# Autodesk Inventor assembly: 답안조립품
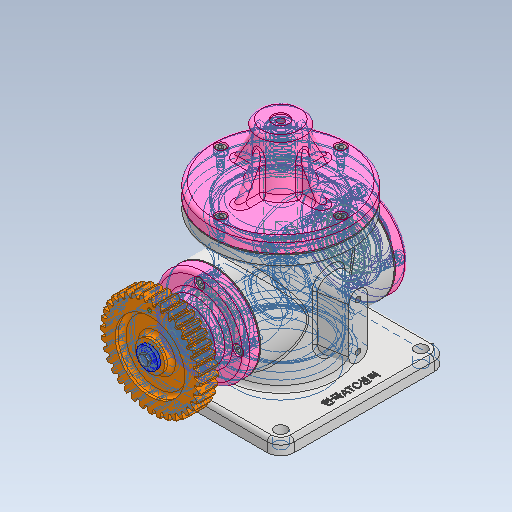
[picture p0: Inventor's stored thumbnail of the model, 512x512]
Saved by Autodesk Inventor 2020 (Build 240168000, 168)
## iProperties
Created: 2020-12
Part Number: 답안조립품
Document SubType Name: Assembly
Designer: USER
Author: USER
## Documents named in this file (21)
- C:\Users\USER\Desktop\601206V1034\답안조립품.iam
- C:\Users\USER\Desktop\601206V1034\본체.ipt
- C:\Users\USER\Desktop\601206V1034\E-링.ipt
- C:\Users\USER\Desktop\601206V1034\개스킷 A.ipt
- C:\Users\USER\Desktop\601206V1034\개스킷 B.ipt
- C:\Users\USER\Desktop\601206V1034\덮개.ipt
- C:\Users\USER\Desktop\601206V1034\뒤커버.ipt
- C:\Users\USER\Desktop\601206V1034\링크.ipt
- C:\Users\USER\Desktop\601206V1034\베어링 17 x 40 x 12.ipt
- C:\Users\USER\Desktop\601206V1034\볼트 M4 x 10.ipt
- C:\Users\USER\Desktop\601206V1034\스퍼기어.ipt
- C:\Users\USER\Desktop\601206V1034\슬라이더.ipt
- C:\Users\USER\Desktop\601206V1034\앞커버.ipt
- C:\Users\USER\Desktop\601206V1034\오일 실 17 30 8.ipt
- C:\Users\USER\Desktop\601206V1034\와셔 4x16.ipt
- C:\Users\USER\Desktop\601206V1034\육각 소켓 머리 볼트 M4 x 10.ipt
- C:\Users\USER\Desktop\601206V1034\클레비스 핀 6 x 22.ipt
- 클레비스 핀 6 x 22.ipt
- C:\Users\USER\Desktop\601206V1034\키 4 x 4 x 18.ipt
- C:\Users\USER\Desktop\601206V1034\편심축.ipt
- C:\Users\USER\Desktop\601206V1034\가변스프링.ipt
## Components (5 placed, 4 different names)
1. E-링:1
2. 개스킷 A:1
3. 개스킷 B:1
4. 가변스프링:1
5. 개스킷 A:2
